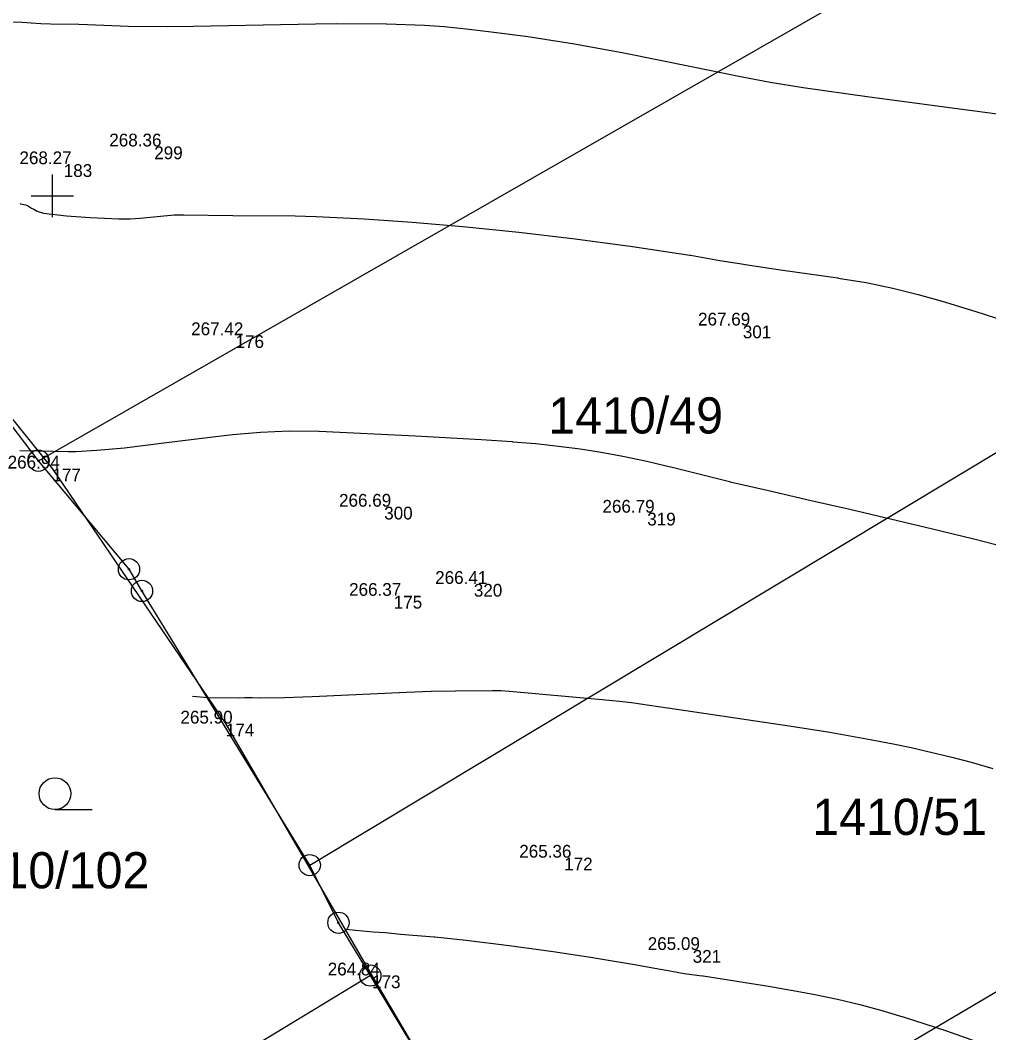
# Model space of a CAD drawing. Extents: x -771260 to -770828, y -1053564 to -1052811.
# Drawn here: x -771201.51 to -771155.95, y -1053239.34 to -1053191.74 of the extents above; entities that cross this region are included whole.
import ezdxf

# ---------------------------------------------------------------- set-up
doc = ezdxf.new("R2010")
doc.units = 0
for name, color, linetype in [('14_8_2023_krizky', 7, 'Continuous'), ('25_3_2019_krizky_JTSK', 7, 'Continuous'), ('25_3_2019_oploceni', 7, 'Continuous'), ('25_3_2019_vrstevnice_interval_po_1m', 7, 'Continuous'), ('25_3_2019_zamereny_bod', 7, 'Continuous'), ('25_3_2019_zamereny_bod_cislo', 7, 'Continuous'), ('25_3_2019_zamereny_bod_vyska', 7, 'Continuous'), ('Default', 7, 'Continuous'), ('DKM_Hranice parcel', 7, 'Continuous'), ('DKM_Parcelní čísla', 7, 'Continuous'), ('DKM_Značky bodu BP', 7, 'Continuous'), ('DKM_Značky kultur', 7, 'Continuous')]:
    doc.layers.add(name, color=color, linetype=linetype)

# ---------------------------------------------------------------- blocks, each defined once
blk = doc.blocks.new('POINT_DISPLAY')
at = {"layer": 'Default'}
blk.add_line((0, 0), (0, 0), dxfattribs=at)
blk = doc.blocks.new('KRIZEK')
at = {"layer": '25_3_2019_krizky_JTSK'}
for p, q in [((0, 10), (0, -10)), ((-10, 0), (10, 0))]:
    blk.add_line(p, q, dxfattribs=at)

msp = doc.modelspace()

# ---------------------------------------------------------------- linework, layer by layer
at = {"layer": '25_3_2019_oploceni'}
for p, q in [((-771199.993, -1053212.815), (-771203.558, -1053208.384)), ((-771191.837, -1053224.805), (-771199.993, -1053212.815)), ((-771184.958, -1053236.643), (-771191.837, -1053224.805)), ((-771175.871, -1053252.03), (-771184.958, -1053236.643))]:
    msp.add_line(p, q, dxfattribs=at)
at = {"layer": '25_3_2019_vrstevnice_interval_po_1m'}
for points in [[(-771202.457, -1053191.813), (-771201.422, -1053191.837), (-771201, -1053191.869), (-771200.537, -1053191.903), (-771200.088, -1053191.918), (-771198.752, -1053191.925), (-771198.336, -1053191.942), (-771196.43, -1053192.017), (-771194.57, -1053192.039), (-771193.359, -1053192.026), (-771193.356, -1053192.026), (-771187.626, -1053191.915), (-771186.608, -1053191.901), (-771184.297, -1053191.914), (-771184.264, -1053191.915), (-771182.492, -1053191.97), (-771181.556, -1053192.041), (-771181.547, -1053192.042), (-771180.398, -1053192.157), (-771179.364, -1053192.282), (-771177.746, -1053192.494), (-771177.723, -1053192.497), (-771176.84, -1053192.629), (-771175.44, -1053192.854), (-771173.113, -1053193.272), (-771169.936, -1053193.914), (-771167.623, -1053194.395), (-771166.231, -1053194.655), (-771166.228, -1053194.655), (-771164.678, -1053194.909), (-771161.57, -1053195.347), (-771151.899, -1053196.622)], [(-771201.422, -1053191.837), (-771201.422, -1053191.837)], [(-771200.537, -1053191.903), (-771200.537, -1053191.903)], [(-771200.088, -1053191.918), (-771200.088, -1053191.918)], [(-771198.752, -1053191.925), (-771198.752, -1053191.925)], [(-771196.43, -1053192.017), (-771196.43, -1053192.017)], [(-771194.57, -1053192.039), (-771194.57, -1053192.039)], [(-771193.359, -1053192.026), (-771193.359, -1053192.026)], [(-771187.626, -1053191.915), (-771187.626, -1053191.915)], [(-771186.608, -1053191.901), (-771186.608, -1053191.901)], [(-771184.297, -1053191.914), (-771184.297, -1053191.914)], [(-771182.492, -1053191.97), (-771182.492, -1053191.97)], [(-771181.556, -1053192.041), (-771181.556, -1053192.041)], [(-771180.398, -1053192.157), (-771180.398, -1053192.157)], [(-771179.364, -1053192.282), (-771179.364, -1053192.282)], [(-771177.723, -1053192.497), (-771177.723, -1053192.497)], [(-771176.84, -1053192.629), (-771176.84, -1053192.629)], [(-771175.44, -1053192.854), (-771175.44, -1053192.854)], [(-771173.113, -1053193.272), (-771173.113, -1053193.272)], [(-771169.936, -1053193.914), (-771169.936, -1053193.914)], [(-771167.623, -1053194.395), (-771167.623, -1053194.395)], [(-771166.228, -1053194.655), (-771166.228, -1053194.655)], [(-771164.678, -1053194.909), (-771164.678, -1053194.909)], [(-771161.57, -1053195.347), (-771161.57, -1053195.347)], [(-771201.509, -1053200.363), (-771201.494, -1053200.366), (-771201.264, -1053200.415), (-771201.18, -1053200.447), (-771201.171, -1053200.453), (-771200.973, -1053200.572), (-771200.872, -1053200.619), (-771200.707, -1053200.716), (-771200.419, -1053200.811), (-771200.416, -1053200.811), (-771199.331, -1053200.938), (-771198.223, -1053201.02), (-771196.871, -1053201.084), (-771196.844, -1053201.085), (-771196.336, -1053201.083), (-771195.858, -1053201.052), (-771194.263, -1053200.897), (-771193.82, -1053200.887), (-771193.806, -1053200.887), (-771191.507, -1053200.916), (-771188.573, -1053200.941), (-771187.605, -1053200.964), (-771187.595, -1053200.965), (-771185.324, -1053201.074), (-771183.074, -1053201.23), (-771180.682, -1053201.435), (-771178.061, -1053201.702), (-771175.406, -1053202.014), (-771172.715, -1053202.374), (-771170.007, -1053202.786), (-771169.983, -1053202.789), (-771168.596, -1053203.03), (-771167.676, -1053203.179), (-771167.201, -1053203.264), (-771167.199, -1053203.264), (-771165.646, -1053203.499), (-771163.058, -1053203.859), (-771163.029, -1053203.863), (-771161.72, -1053204.079), (-771160.468, -1053204.342), (-771159.279, -1053204.637), (-771158.138, -1053204.956), (-771156.559, -1053205.442), (-771153.788, -1053206.335)], [(-771201.264, -1053200.415), (-771201.264, -1053200.415)], [(-771201.18, -1053200.447), (-771201.18, -1053200.447)], [(-771200.973, -1053200.572), (-771200.973, -1053200.572)], [(-771200.872, -1053200.619), (-771200.872, -1053200.619)], [(-771200.707, -1053200.716), (-771200.707, -1053200.716)], [(-771200.419, -1053200.811), (-771200.419, -1053200.811)], [(-771199.331, -1053200.938), (-771199.331, -1053200.938)], [(-771198.223, -1053201.02), (-771198.223, -1053201.02)], [(-771196.844, -1053201.085), (-771196.844, -1053201.085)], [(-771196.336, -1053201.083), (-771196.336, -1053201.083)], [(-771195.858, -1053201.052), (-771195.858, -1053201.052)], [(-771194.263, -1053200.897), (-771194.263, -1053200.897)], [(-771193.806, -1053200.887), (-771193.806, -1053200.887)], [(-771191.507, -1053200.916), (-771191.507, -1053200.916)], [(-771188.573, -1053200.941), (-771188.573, -1053200.941)], [(-771187.605, -1053200.964), (-771187.605, -1053200.964)], [(-771185.324, -1053201.074), (-771185.324, -1053201.074)], [(-771183.074, -1053201.23), (-771183.074, -1053201.23)], [(-771180.682, -1053201.435), (-771180.682, -1053201.435)], [(-771178.061, -1053201.702), (-771178.061, -1053201.702)], [(-771175.406, -1053202.014), (-771175.406, -1053202.014)], [(-771172.715, -1053202.374), (-771172.715, -1053202.374)], [(-771169.983, -1053202.789), (-771169.983, -1053202.789)], [(-771168.596, -1053203.03), (-771168.596, -1053203.03)], [(-771167.676, -1053203.179), (-771167.676, -1053203.179)], [(-771167.199, -1053203.264), (-771167.199, -1053203.264)], [(-771165.646, -1053203.499), (-771165.646, -1053203.499)], [(-771163.058, -1053203.859), (-771163.058, -1053203.859)], [(-771161.72, -1053204.079), (-771161.72, -1053204.079)], [(-771160.468, -1053204.342), (-771160.468, -1053204.342)], [(-771159.279, -1053204.637), (-771159.279, -1053204.637)], [(-771158.138, -1053204.956), (-771158.138, -1053204.956)], [(-771156.559, -1053205.442), (-771156.559, -1053205.442)], [(-771201.533, -1053211.976), (-771200.657, -1053211.991), (-771199.249, -1053212.015), (-771198.911, -1053212.011), (-771198.884, -1053212.009), (-771197.91, -1053211.95), (-771196.604, -1053211.837), (-771194.755, -1053211.616), (-771192.57, -1053211.341), (-771191.517, -1053211.223), (-771190.209, -1053211.111), (-771188.857, -1053211.049), (-771187.464, -1053211.064), (-771187.44, -1053211.064), (-771182.915, -1053211.282), (-771179.824, -1053211.455), (-771178.372, -1053211.553), (-771178.339, -1053211.556), (-771177.26, -1053211.645), (-771176.197, -1053211.761), (-771175.176, -1053211.898), (-771174.191, -1053212.054), (-771173.17, -1053212.241), (-771172.04, -1053212.477), (-771170.919, -1053212.733), (-771170.914, -1053212.734), (-771169.59, -1053213.064), (-771168.148, -1053213.429), (-771168.115, -1053213.437), (-771166.376, -1053213.833), (-771164.301, -1053214.322), (-771162.489, -1053214.733), (-771158.601, -1053215.645), (-771156.655, -1053216.124), (-771154.707, -1053216.624)], [(-771190.209, -1053211.111), (-771190.209, -1053211.111)], [(-771188.857, -1053211.049), (-771188.857, -1053211.049)], [(-771187.44, -1053211.064), (-771187.44, -1053211.064)], [(-771194.755, -1053211.616), (-771194.755, -1053211.616)], [(-771192.57, -1053211.341), (-771192.57, -1053211.341)], [(-771191.517, -1053211.223), (-771191.517, -1053211.223)], [(-771182.915, -1053211.282), (-771182.915, -1053211.282)], [(-771179.824, -1053211.455), (-771179.824, -1053211.455)], [(-771178.372, -1053211.553), (-771178.372, -1053211.553)], [(-771177.26, -1053211.645), (-771177.26, -1053211.645)], [(-771199.249, -1053212.015), (-771199.249, -1053212.015)], [(-771198.911, -1053212.011), (-771198.911, -1053212.011)], [(-771197.91, -1053211.95), (-771197.91, -1053211.95)], [(-771196.604, -1053211.837), (-771196.604, -1053211.837)], [(-771176.197, -1053211.761), (-771176.197, -1053211.761)], [(-771175.176, -1053211.898), (-771175.176, -1053211.898)], [(-771174.191, -1053212.054), (-771174.191, -1053212.054)], [(-771173.17, -1053212.241), (-771173.17, -1053212.241)], [(-771172.04, -1053212.477), (-771172.04, -1053212.477)], [(-771170.919, -1053212.733), (-771170.919, -1053212.733)], [(-771169.59, -1053213.064), (-771169.59, -1053213.064)], [(-771168.148, -1053213.429), (-771168.148, -1053213.429)], [(-771166.376, -1053213.833), (-771166.376, -1053213.833)], [(-771164.301, -1053214.322), (-771164.301, -1053214.322)], [(-771162.489, -1053214.733), (-771162.489, -1053214.733)], [(-771158.601, -1053215.645), (-771158.601, -1053215.645)], [(-771156.655, -1053216.124), (-771156.655, -1053216.124)], [(-771193.397, -1053223.517), (-771192.671, -1053223.579), (-771192.65, -1053223.58), (-771191.206, -1053223.589), (-771190.95, -1053223.577), (-771190.94, -1053223.577), (-771190.601, -1053223.58), (-771190.271, -1053223.597), (-771190.247, -1053223.596), (-771189.075, -1053223.577), (-771187.776, -1053223.54), (-771183.332, -1053223.327), (-771182.18, -1053223.283), (-771181.032, -1053223.261), (-771181.014, -1053223.261), (-771179.298, -1053223.243), (-771178.899, -1053223.252), (-771178.509, -1053223.276), (-771178.496, -1053223.276), (-771174.133, -1053223.681), (-771173.324, -1053223.756), (-771172.749, -1053223.821), (-771171.062, -1053224.063), (-771171.054, -1053224.064), (-771165.341, -1053224.906), (-771163.434, -1053225.211), (-771161.524, -1053225.55), (-771160.442, -1053225.761), (-771159.609, -1053225.935), (-771157.687, -1053226.385), (-771156.784, -1053226.62), (-771155.757, -1053226.91)], [(-771193.397, -1053223.517), (-771193.397, -1053223.517)], [(-771187.776, -1053223.54), (-771187.776, -1053223.54)], [(-771183.332, -1053223.327), (-771183.332, -1053223.327)], [(-771182.18, -1053223.283), (-771182.18, -1053223.283)], [(-771181.014, -1053223.261), (-771181.014, -1053223.261)], [(-771179.298, -1053223.243), (-771179.298, -1053223.243)], [(-771178.899, -1053223.252), (-771178.899, -1053223.252)], [(-771178.496, -1053223.276), (-771178.496, -1053223.276)], [(-771192.65, -1053223.58), (-771192.65, -1053223.58)], [(-771191.206, -1053223.589), (-771191.206, -1053223.589)], [(-771190.95, -1053223.577), (-771190.95, -1053223.577)], [(-771190.601, -1053223.58), (-771190.601, -1053223.58)], [(-771190.271, -1053223.597), (-771190.271, -1053223.597)], [(-771189.075, -1053223.577), (-771189.075, -1053223.577)], [(-771173.324, -1053223.756), (-771173.324, -1053223.756)], [(-771172.749, -1053223.821), (-771172.749, -1053223.821)], [(-771171.054, -1053224.064), (-771171.054, -1053224.064)], [(-771165.341, -1053224.906), (-771165.341, -1053224.906)], [(-771163.434, -1053225.211), (-771163.434, -1053225.211)], [(-771161.524, -1053225.55), (-771161.524, -1053225.55)], [(-771160.442, -1053225.761), (-771160.442, -1053225.761)], [(-771159.609, -1053225.935), (-771159.609, -1053225.935)], [(-771157.687, -1053226.385), (-771157.687, -1053226.385)], [(-771156.784, -1053226.62), (-771156.784, -1053226.62)], [(-771186.201, -1053234.475), (-771186.201, -1053234.475)], [(-771186.201, -1053234.475), (-771184.91, -1053234.588), (-771184.323, -1053234.631), (-771183.619, -1053234.702), (-771182.033, -1053234.834), (-771182.008, -1053234.836), (-771180.525, -1053234.992), (-771178.513, -1053235.234), (-771176.442, -1053235.519), (-771174.581, -1053235.8), (-771174.496, -1053235.814), (-771172.611, -1053236.136), (-771171.655, -1053236.308), (-771170.852, -1053236.44), (-771170.277, -1053236.547), (-771170.274, -1053236.547), (-771169.555, -1053236.641), (-771169.4, -1053236.656), (-771169.386, -1053236.657), (-771166.317, -1053237.151), (-771164.984, -1053237.381), (-771164.132, -1053237.545), (-771163.062, -1053237.767), (-771162.015, -1053238.016), (-771160.989, -1053238.29), (-771159.988, -1053238.591), (-771159.977, -1053238.595), (-771157.943, -1053239.256), (-771156.303, -1053239.831)], [(-771184.91, -1053234.588), (-771184.91, -1053234.588)], [(-771184.323, -1053234.631), (-771184.323, -1053234.631)], [(-771183.619, -1053234.702), (-771183.619, -1053234.702)], [(-771182.033, -1053234.834), (-771182.033, -1053234.834)], [(-771180.525, -1053234.992), (-771180.525, -1053234.992)], [(-771178.513, -1053235.234), (-771178.513, -1053235.234)], [(-771176.442, -1053235.519), (-771176.442, -1053235.519)], [(-771174.581, -1053235.8), (-771174.581, -1053235.8)], [(-771172.611, -1053236.136), (-771172.611, -1053236.136)], [(-771171.655, -1053236.308), (-771171.655, -1053236.308)], [(-771170.852, -1053236.44), (-771170.852, -1053236.44)], [(-771170.277, -1053236.547), (-771170.277, -1053236.547)], [(-771169.555, -1053236.641), (-771169.555, -1053236.641)], [(-771169.386, -1053236.657), (-771169.386, -1053236.657)], [(-771166.317, -1053237.151), (-771166.317, -1053237.151)], [(-771164.984, -1053237.381), (-771164.984, -1053237.381)], [(-771164.132, -1053237.545), (-771164.132, -1053237.545)], [(-771163.062, -1053237.767), (-771163.062, -1053237.767)], [(-771162.015, -1053238.016), (-771162.015, -1053238.016)], [(-771160.989, -1053238.29), (-771160.989, -1053238.29)], [(-771159.988, -1053238.591), (-771159.988, -1053238.591)], [(-771157.943, -1053239.256), (-771157.943, -1053239.256)]]:
    msp.add_lwpolyline(points, dxfattribs=at)
at = {"layer": 'DKM_Hranice parcel'}
for p, q in [((-771200.65, -1053212.45), (-771157.58, -1053187.8)), ((-771187.89, -1053231.46), (-771145.98, -1053206.27)), ((-771176.96, -1053249.99), (-771134.3, -1053224.85)), ((-771185.04, -1053236.65), (-771206.03, -1053249.37)), ((-771176.96, -1053249.99), (-771185.04, -1053236.65))]:
    msp.add_line(p, q, dxfattribs=at)
for points in [[(-771200.65, -1053212.45), (-771203.18, -1053209.13), (-771206.22, -1053205.48), (-771207.03, -1053203.79)], [(-771187.89, -1053231.46), (-771195.78, -1053218.57), (-771196.39, -1053217.55), (-771200.65, -1053212.45)], [(-771185.04, -1053236.65), (-771186.54, -1053234.17), (-771187.89, -1053231.46)]]:
    msp.add_lwpolyline(points, dxfattribs=at)
at = {"layer": 'DKM_Značky bodu BP'}
for centre, radius in [((-771200.65, -1053212.45), 0.5), ((-771200.65, -1053212.45), 0.0303), ((-771196.39, -1053217.55), 0.5), ((-771196.39, -1053217.55), 0.0303), ((-771195.78, -1053218.57), 0.5), ((-771195.78, -1053218.57), 0.0303), ((-771187.89, -1053231.46), 0.5), ((-771187.89, -1053231.46), 0.0303), ((-771186.54, -1053234.17), 0.5), ((-771186.54, -1053234.17), 0.0303), ((-771185.04, -1053236.65), 0.5), ((-771185.04, -1053236.65), 0.0303)]:
    msp.add_circle(centre, radius, dxfattribs=at)
at = {"layer": 'DKM_Značky kultur'}
msp.add_line((-771199.873, -1053228.85), (-771198.123, -1053228.85), dxfattribs=at)
msp.add_circle((-771199.873, -1053228.1), 0.75, dxfattribs=at)

# ---------------------------------------------------------------- block references
at = {"layer": '14_8_2023_krizky', "xscale": 0.1, "yscale": 0.10000000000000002}
msp.add_blockref('KRIZEK', (-771200, -1053200), dxfattribs=at)
at = {"layer": '25_3_2019_zamereny_bod', "xscale": 0.1, "yscale": 0.10000000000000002}
for p in [(-771195.204, -1053197.675), (-771199.46, -1053198.508), (-771167.52, -1053206.093), (-771191.38, -1053206.548), (-771199.993, -1053212.816), (-771184.388, -1053214.61), (-771172.016, -1053214.892), (-771180.172, -1053218.239), (-771183.938, -1053218.8), (-771191.837, -1053224.805), (-771175.922, -1053231.108), (-771169.877, -1053235.448), (-771184.958, -1053236.644)]:
    msp.add_blockref('POINT_DISPLAY', p, dxfattribs=at)

# ---------------------------------------------------------------- texts
at = {"layer": '25_3_2019_zamereny_bod_cislo'}
for s, p in [('299', (-771195.204, -1053198.275)), ('183', (-771199.46, -1053199.108)), ('301', (-771167.52, -1053206.693)), ('176', (-771191.38, -1053207.148)), ('177', (-771199.993, -1053213.416)), ('300', (-771184.388, -1053215.21)), ('319', (-771172.016, -1053215.492)), ('320', (-771180.172, -1053218.839)), ('175', (-771183.938, -1053219.4)), ('174', (-771191.837, -1053225.405)), ('172', (-771175.922, -1053231.708)), ('321', (-771169.877, -1053236.048)), ('173', (-771184.958, -1053237.244))]:
    msp.add_text(s, height=0.6, dxfattribs=at).set_placement(p)
at = {"layer": '25_3_2019_zamereny_bod_vyska'}
for s, p in [('268.36 ', (-771197.318, -1053197.675)), ('268.27 ', (-771201.544, -1053198.508)), ('267.42 ', (-771193.466, -1053206.548)), ('267.69 ', (-771169.627, -1053206.093)), ('266.94 ', (-771202.099, -1053212.816)), ('266.69 ', (-771186.512, -1053214.61)), ('266.79 ', (-771174.123, -1053214.892)), ('266.41 ', (-771181.991, -1053218.239)), ('266.37 ', (-771186.039, -1053218.8)), ('265.90 ', (-771193.971, -1053224.805)), ('265.36 ', (-771178.036, -1053231.108)), ('265.09 ', (-771171.993, -1053235.448)), ('264.84 ', (-771187.044, -1053236.644))]:
    msp.add_text(s, height=0.6, dxfattribs=at).set_placement(p)
at = {"layer": 'DKM_Parcelní čísla'}
for s, p in [('1410/49', (-771176.67, -1053211.17)), ('1410/51', (-771164.256, -1053230.04)), ('1410/102', (-771204.915, -1053232.55))]:
    msp.add_text(s, height=1.7, dxfattribs=at).set_placement(p)

doc.saveas('drawing.dxf')
